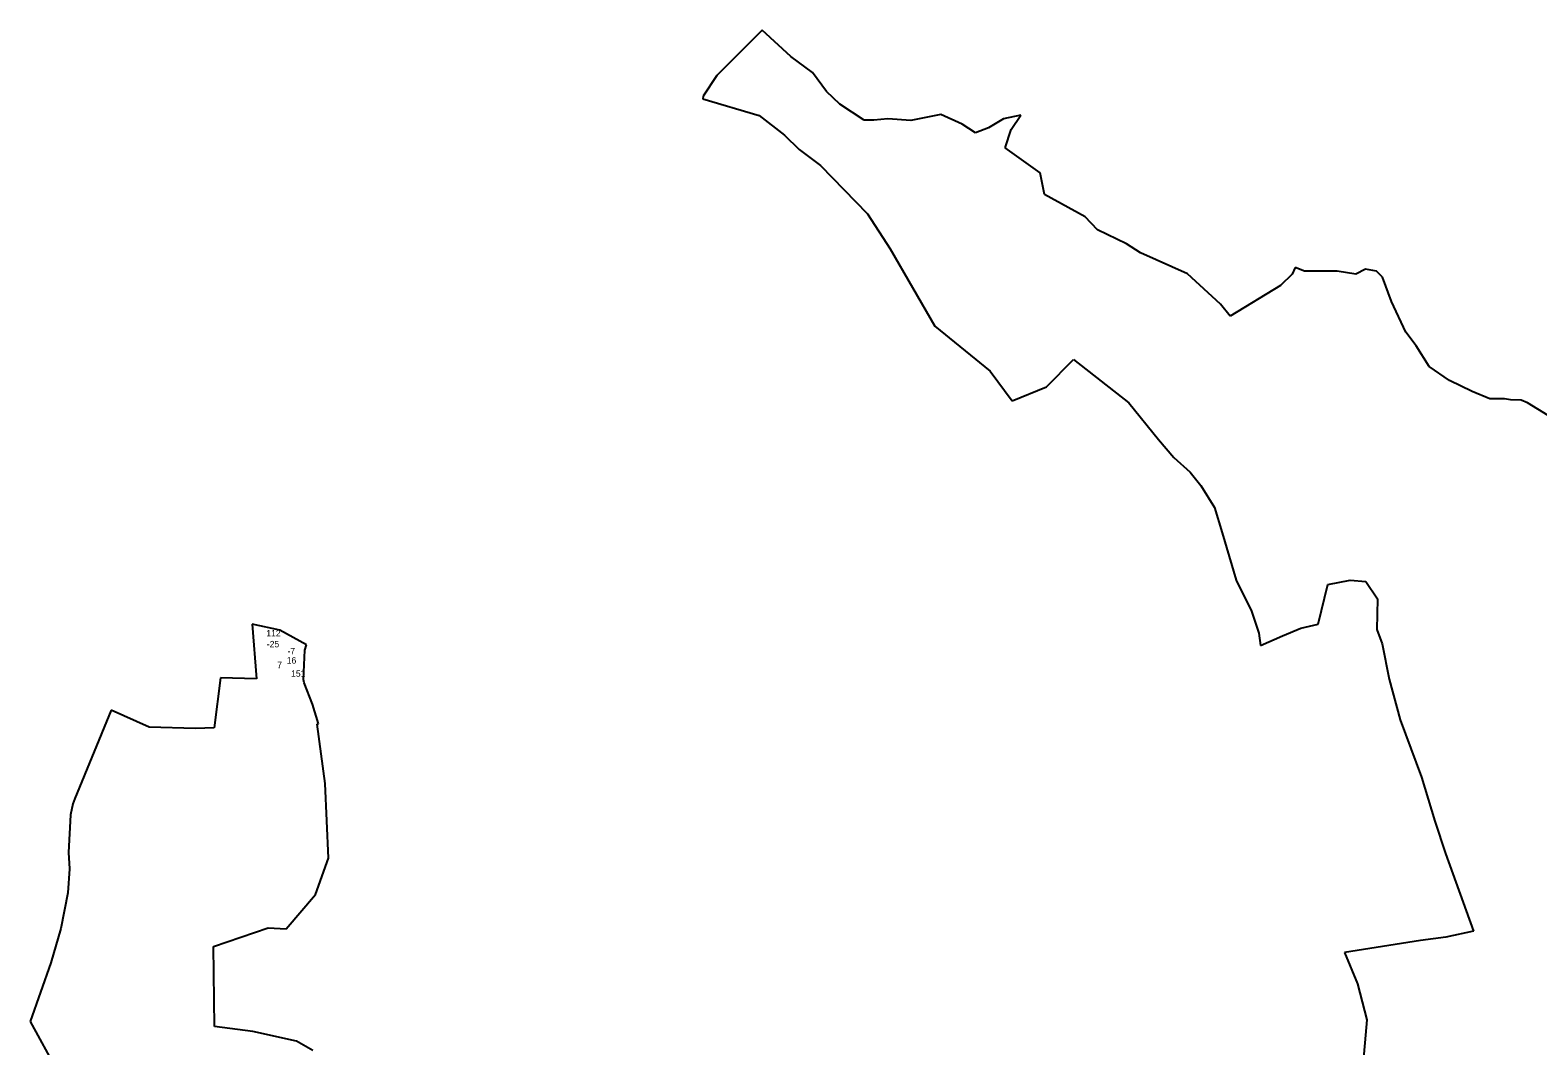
# Model space of a CAD drawing. Extents: x -787692 to -782531, y -972586 to -966265.
# Drawn here: x -787692 to -785345, y -967846 to -966265 of the extents above; entities that cross this region are included whole.
import ezdxf

# ---------------------------------------------------------------- set-up
doc = ezdxf.new("R2010")
doc.units = 0
doc.layers.add('Vrstva 13', color=7, linetype='Continuous')
doc.layers.add('Vrstva 15', color=7, linetype='Continuous')

msp = doc.modelspace()

# ---------------------------------------------------------------- linework, layer by layer
at = {"layer": 'Vrstva 13'}
for p, q in [((-786552.53, -966265.23), (-786623.07, -966335.65)), ((-786507.92, -966306.38), (-786552.53, -966265.23)), ((-786474.47, -966331.16), (-786507.92, -966306.38)), ((-786623.07, -966335.65), (-786644.2, -966368.18)), ((-786452.45, -966360.57), (-786474.47, -966331.16)), ((-786644.2, -966368.18), (-786645.13, -966372.11)), ((-786645.13, -966372.11), (-786557.09, -966397.79)), ((-786431.89, -966380.28), (-786452.45, -966360.57)), ((-786393.65, -966405.49), (-786431.89, -966380.28)), ((-786557.09, -966397.79), (-786517.75, -966428.44)), ((-786378.87, -966405.2), (-786393.65, -966405.49)), ((-786357.15, -966403.46), (-786378.87, -966405.2)), ((-786321.23, -966405.78), (-786357.15, -966403.46)), ((-786274.6, -966396.22), (-786321.23, -966405.78)), ((-786240.99, -966411.28), (-786274.6, -966396.22)), ((-786220.72, -966424.9), (-786240.99, -966411.28)), ((-786200.15, -966417.37), (-786220.72, -966424.9)), ((-786176.97, -966403.17), (-786200.15, -966417.37)), ((-786149.74, -966397.37), (-786176.97, -966403.17)), ((-786164.81, -966419.98), (-786149.74, -966397.37)), ((-786517.75, -966428.44), (-786494.89, -966450.93)), ((-786174.08, -966448.09), (-786164.81, -966419.98)), ((-786494.89, -966450.93), (-786461.55, -966476.04)), ((-786119.91, -966487.5), (-786174.08, -966448.09)), ((-786461.55, -966476.04), (-786388.86, -966551)), ((-786113.24, -966521.11), (-786119.91, -966487.5)), ((-786049.81, -966555.59), (-786113.24, -966521.11)), ((-786388.86, -966551), (-786353.27, -966605.72)), ((-786030.4, -966576.16), (-786049.81, -966555.59)), ((-785985.21, -966597.61), (-786030.4, -966576.16)), ((-786353.27, -966605.72), (-786283.59, -966725.75)), ((-785963.49, -966611.52), (-785985.21, -966597.61)), ((-785890.49, -966644.57), (-785963.49, -966611.52)), ((-785839.21, -966691.51), (-785890.49, -966644.57)), ((-785727.4, -966645.15), (-785745.94, -966662.82)), ((-785723.04, -966634.43), (-785727.4, -966645.15)), ((-785708.27, -966640.51), (-785723.04, -966634.43)), ((-785657.58, -966640.51), (-785708.27, -966640.51)), ((-785628.32, -966644.86), (-785657.58, -966640.51)), ((-785613.54, -966637.33), (-785628.32, -966644.86)), ((-785596.45, -966640.22), (-785613.54, -966637.33)), ((-785586.89, -966649.79), (-785596.45, -966640.22)), ((-785572.99, -966687.46), (-785586.89, -966649.79)), ((-785745.94, -966662.82), (-785824.15, -966710.35)), ((-785824.15, -966710.35), (-785839.21, -966691.51)), ((-785550.39, -966734.98), (-785572.99, -966687.46)), ((-786283.59, -966725.75), (-786197.42, -966795.65)), ((-785534.45, -966756.43), (-785550.39, -966734.98)), ((-785514.47, -966788.59), (-785534.45, -966756.43)), ((-786110.13, -966820.3), (-786067.79, -966777.95)), ((-786067.79, -966777.95), (-785981.62, -966845.41)), ((-785482.89, -966810.62), (-785514.47, -966788.59)), ((-786197.42, -966795.65), (-786163.32, -966842.03)), ((-785447.26, -966827.71), (-785482.89, -966810.62)), ((-786163.32, -966842.03), (-786110.13, -966820.3)), ((-785419.74, -966839.02), (-785447.26, -966827.71)), ((-785397.14, -966838.73), (-785419.74, -966839.02)), ((-785387.87, -966840.47), (-785397.14, -966838.73)), ((-785371.07, -966841.05), (-785387.87, -966840.47)), ((-785361.22, -966845.4), (-785371.07, -966841.05)), ((-785981.62, -966845.41), (-785935.54, -966902.01)), ((-785329.07, -966864.81), (-785361.22, -966845.4)), ((-785935.54, -966902.01), (-785911.56, -966930.12)), ((-785911.56, -966930.12), (-785886.46, -966952.98)), ((-785886.46, -966952.98), (-785869.98, -966973.6)), ((-785869.98, -966973.6), (-785848.62, -967008.08)), ((-785848.62, -967008.08), (-785836.63, -967047.43)), ((-785836.63, -967047.43), (-785814.9, -967121.26)), ((-785814.9, -967121.26), (-785790.92, -967169.61)), ((-785672.16, -967128.01), (-785637.31, -967121.26)), ((-785637.31, -967121.26), (-785612.96, -967123.14)), ((-785612.96, -967123.14), (-785594.6, -967150.12)), ((-785687.14, -967189.48), (-785672.16, -967128.01)), ((-785790.92, -967169.61), (-785779.31, -967203.34)), ((-785594.6, -967150.12), (-785595.72, -967198.1)), ((-787303.17, -967198.97), (-787346.22, -967189.49)), ((-787346.22, -967189.49), (-787339.9, -967274.47)), ((-785714.12, -967195.85), (-785687.14, -967189.48)), ((-787261.7, -967221.81), (-787303.17, -967198.97)), ((-785779.31, -967203.34), (-785776.69, -967222.83)), ((-785776.69, -967222.83), (-785742.59, -967207.84)), ((-785742.59, -967207.84), (-785714.12, -967195.85)), ((-785595.72, -967198.1), (-785587.48, -967220.21)), ((-787266.75, -967275.69), (-787264.32, -967230.06)), ((-787264.32, -967230.06), (-787261.7, -967221.81)), ((-785587.48, -967220.21), (-785576.63, -967274.93)), ((-787395.87, -967273.04), (-787405.62, -967351.13)), ((-787339.9, -967274.47), (-787395.87, -967273.04)), ((-787265.63, -967280.94), (-787266.75, -967275.69)), ((-787252.51, -967313.92), (-787265.63, -967280.94)), ((-785576.63, -967274.93), (-785559.39, -967338.65)), ((-787565.76, -967323.28), (-787622.58, -967460.8)), ((-787506.93, -967349.69), (-787565.76, -967323.28)), ((-787243.15, -967344.66), (-787252.51, -967313.92)), ((-787434.9, -967351.99), (-787506.93, -967349.69)), ((-787405.62, -967351.13), (-787434.9, -967351.99)), ((-787245.03, -967345.4), (-787243.15, -967344.66)), ((-787233.04, -967437.61), (-787245.03, -967345.4)), ((-785559.39, -967338.65), (-785526.42, -967427.48)), ((-785526.42, -967427.48), (-785505.44, -967496.07)), ((-787227.79, -967553.79), (-787233.04, -967437.61)), ((-787625.73, -967469.41), (-787629.18, -967486.35)), ((-787622.58, -967460.8), (-787625.73, -967469.41)), ((-787629.18, -967486.35), (-787632.41, -967544.85)), ((-785505.44, -967496.07), (-785488.96, -967546.29)), ((-787632.41, -967544.85), (-787630.69, -967570.54)), ((-787247.64, -967610.38), (-787227.79, -967553.79)), ((-785488.96, -967546.29), (-785445.13, -967667.17)), ((-787630.69, -967570.54), (-787633.13, -967607.72)), ((-787633.13, -967607.72), (-787644.24, -967662.92)), ((-787293.73, -967663.61), (-787247.64, -967610.38)), ((-787644.24, -967662.92), (-787659.59, -967716.75)), ((-787406.5, -967690.97), (-787321.46, -967662.11)), ((-787321.46, -967662.11), (-787293.73, -967663.61)), ((-785527.56, -967681.6), (-785646.32, -967700.34)), ((-785488.22, -967676.73), (-785527.56, -967681.6)), ((-785445.13, -967667.17), (-785488.22, -967676.73)), ((-787405.01, -967815.78), (-787406.5, -967690.97)), ((-785646.32, -967700.34), (-785625.72, -967749.44)), ((-787659.59, -967716.75), (-787692.02, -967808.05)), ((-785625.72, -967749.44), (-785611.11, -967805.28)), ((-787692.02, -967808.05), (-787650.12, -967884.42)), ((-787345.44, -967823.66), (-787405.01, -967815.78)), ((-787277.63, -967838.27), (-787345.44, -967823.66)), ((-785611.11, -967805.28), (-785618.22, -967882.5)), ((-787251.77, -967853.26), (-787277.63, -967838.27))]:
    msp.add_line(p, q, dxfattribs=at)

# ---------------------------------------------------------------- texts
at = {"layer": 'Vrstva 15'}
for s, p in [('112', (-787324.436, -967208.71)), ('-25', (-787323.68, -967225.63)), ('16', (-787292.624, -967250.9)), ('-7', (-787291.489, -967236.48)), ('7', (-787307.496, -967258.11)), ('151', (-787285.846, -967271.38))]:
    msp.add_text(s, height=10, dxfattribs=at).set_placement(p)

doc.saveas('drawing.dxf')
